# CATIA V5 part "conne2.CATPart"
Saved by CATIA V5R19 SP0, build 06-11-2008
Part number: Part1
Bounding box of the stored display mesh (mm): x -70.936 to 70.936, y -189.522 to -49.522, z -141.819 to -0.093
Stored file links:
  C:\Documents and Settings\Administrateur\Bureau\projet I\conne2.CATPart
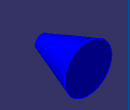
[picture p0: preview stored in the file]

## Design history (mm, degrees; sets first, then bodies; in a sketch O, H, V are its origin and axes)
Body1 (main body)
  Sketch1 on yz-plane, origin (0, 0, 0), H (0, 1, 0), V (0, 0, 1)
    point P1 (-49.5216, 0)
    point P2 (-49.5216, 0)
    line L1 (-49.5216, 0) -> (-189.5216, -50.9558)
    line L2 (-189.5216, -50.9558) -> (-189.5216, -70.9558)
    line L3 (-189.5216, -70.9558) -> (-49.5216, -70.9558)
    line L4 (-49.5216, -70.9558) -> (-49.5216, 0)
    length L3 = 140
    angle L3 L1 = 20
    length L2 = 20
    coincidence: P1 H, P2 P1
    vertical: L2 V, L4 V
    horizontal: L3 H
  Shaft1: profile Sketch1, axis Sketch1.L3, angle 360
